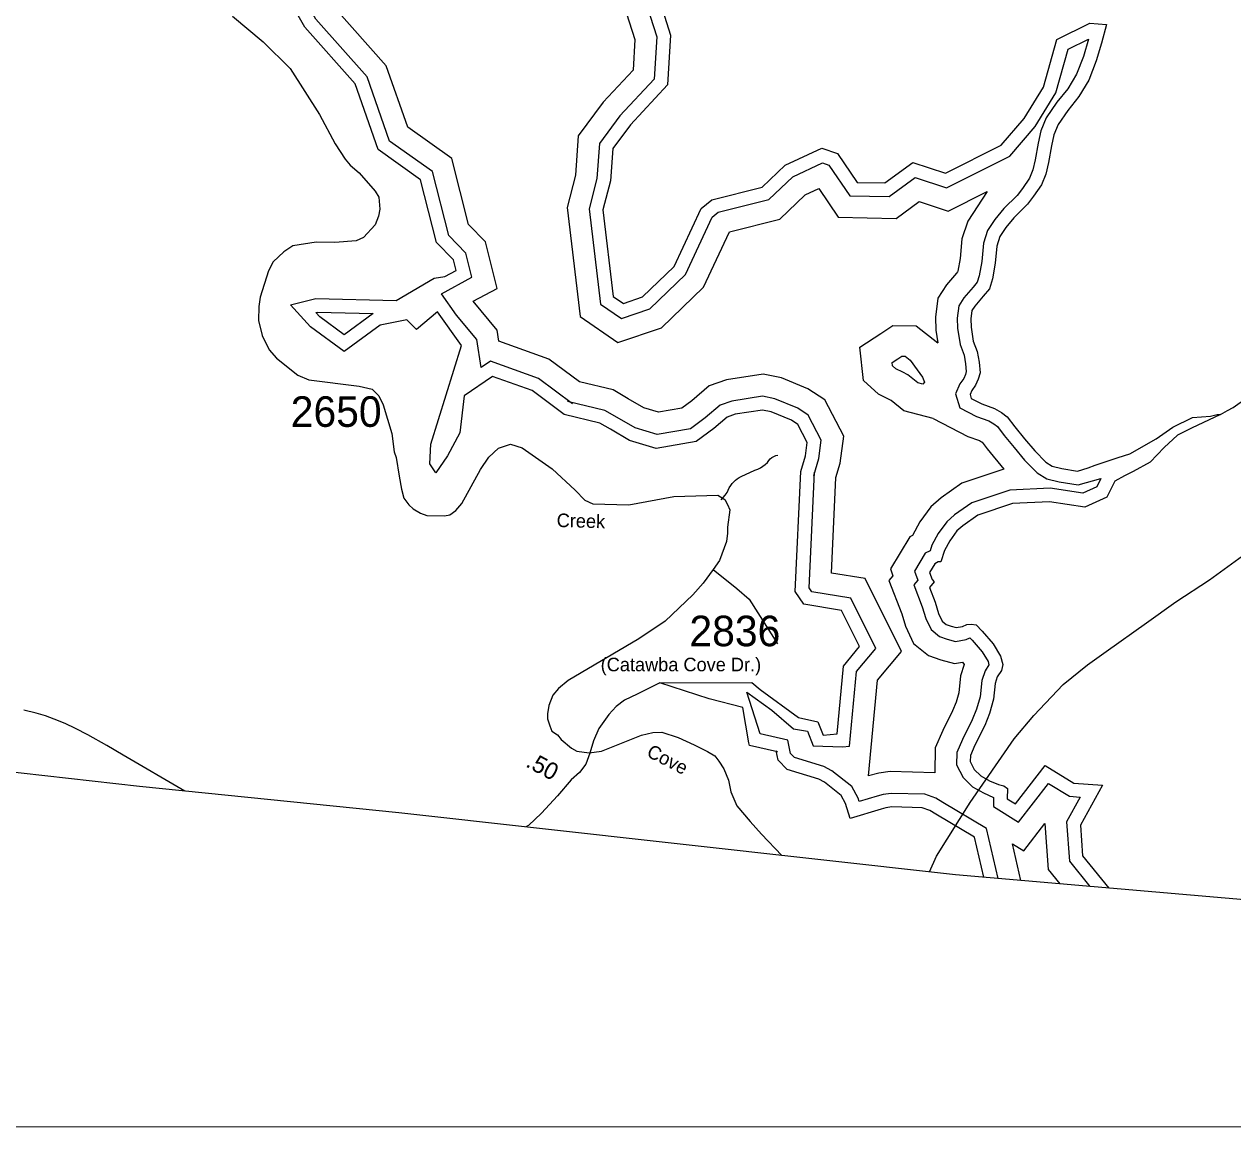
# Model space of a CAD drawing. Extents: x 1268485 to 1426702, y 514839 to 616766.
# Drawn here: x 1380280 to 1386120, y 514851 to 520182 of the extents above; entities that cross this region are included whole.
import ezdxf

# ---------------------------------------------------------------- set-up
doc = ezdxf.new("R2010")
doc.units = 0
for name, color, linetype in [('Old_Level_11', 7, 'Continuous'), ('Old_Level_17', 7, 'Continuous'), ('Old_Level_29', 7, 'Continuous'), ('Old_Level_31', 7, 'Continuous'), ('Old_Level_32', 7, 'Continuous'), ('Old_Level_35', 7, 'Continuous'), ('Old_Level_50', 7, 'Continuous'), ('Old_Level_52', 7, 'Continuous'), ('Old_Level_58', 7, 'Continuous'), ('Old_Level_60', 7, 'Continuous'), ('Old_Level_61', 7, 'Continuous'), ('Old_Level_62', 7, 'Continuous'), ('Old_Level_63', 7, 'Continuous'), ('Old_Level_8', 7, 'Continuous')]:
    doc.layers.add(name, color=color, linetype=linetype)

msp = doc.modelspace()

# ---------------------------------------------------------------- linework, layer by layer
at = {"layer": 'Old_Level_29'}
msp.add_lwpolyline([(1384653.629, 516087.565), (1384687.783, 516162.945), (1384851.453, 516422.625), (1385063.598, 516730.733), (1385159.14, 516843.649), (1385300.192, 516992.785), (1385417.556, 517087.592), (1385507.776, 517152.573), (1385702.319, 517289.991), (1385845.15, 517391.464), (1386007.246, 517498.86), (1386219.95, 517653.243)], dxfattribs=at)
at = {"layer": 'Old_Level_31'}
msp.add_line((1384843.405, 516437.698), (1384843.405, 516437.698), dxfattribs=at)
at = {"layer": 'Old_Level_32'}
for points in [[(1381285.944, 520221.123), (1381434.968, 520095.965), (1381565.364, 519968.144), (1381706.405, 519745.522), (1381783.578, 519604.386), (1381831.479, 519529.824), (1381855.429, 519500.531), (1381898.007, 519463.25), (1381975.603, 519375.82), (1381993.302, 519346.632), (1381998.611, 519288.253), (1381991.532, 519253.913), (1381975.603, 519212.705), (1381918.966, 519150.892), (1381883.568, 519135.439), (1381780.913, 519126.853), (1381690.648, 519128.571), (1381577.816, 519111.329), (1381535.298, 519082.113), (1381483.57, 519034.135), (1381460.561, 518991.21), (1381420.856, 518863.168), (1381414.659, 518818.08), (1381411.56, 518750.448), (1381430.776, 518678.236), (1381464.436, 518609.491), (1381499.867, 518568.244), (1381602.618, 518487.468), (1381655.765, 518463.408), (1381898.007, 518434.292), (1381961.875, 518418.314), (1381993.809, 518386.359), (1382015.393, 518343.104), (1382056.14, 518205.614), (1382068.497, 518116.213), (1382077.399, 518088.747), (1382091.571, 517999.379), (1382103.973, 517935.79), (1382114.602, 517892.824), (1382139.404, 517860.17), (1382158.891, 517841.266), (1382194.323, 517820.641), (1382226.211, 517808.611), (1382311.246, 517806.892), (1382336.048, 517812.048), (1382366.165, 517832.672), (1382394.51, 517867.045), (1382484.86, 518030.314), (1382525.606, 518090.466), (1382571.667, 518133.431), (1382630.129, 518154.055), (1382686.819, 518135.15), (1382831.335, 518034.539), (1382942.322, 517932.017), (1382989.757, 517882.512), (1383026.96, 517865.326), (1383202.346, 517860.17), (1383418.477, 517901.418), (1383631.065, 517906.574), (1383664.726, 517885.95), (1383678.898, 517861.889), (1383689.527, 517836.11), (1383678.399, 517753.002), (1383677.795, 517723), (1383672.989, 517683.078), (1383639.924, 517592.065), (1383609.806, 517547.381)], [(1383609.806, 517547.381), (1383561.283, 517481.772), (1383510.058, 517426.239), (1383377.728, 517298.087), (1383249.668, 517212.651), (1382908.171, 517011.878), (1382861.216, 516973.433), (1382833.859, 516940.706), (1382814.372, 516890.866), (1382809.057, 516851.337), (1382809.057, 516827.276), (1382819.686, 516792.904), (1382830.316, 516767.125), (1382856.948, 516748.737), (1382874.022, 516727.379), (1382925.246, 516684.661), (1382950.783, 516670.882), (1383009.244, 516662.288), (1383069.478, 516670.882), (1383262.578, 516748.007), (1383317.497, 516760.032), (1383361.787, 516761.749), (1383439.736, 516735.981), (1383517.685, 516701.624), (1383581.462, 516668.984), (1383616.893, 516648.369), (1383636.38, 516622.601), (1383661.182, 516584.807), (1383682.441, 516529.834), (1383694.841, 516474.862), (1383723.187, 516406.147), (1383787.523, 516330.105), (1383843.016, 516270.3), (1383940.77, 516167.041)], [(1383609.806, 517547.381), (1383723.493, 517456.142), (1383783.255, 517404.881), (1383920.401, 517189.022)]]:
    msp.add_lwpolyline(points, dxfattribs=at)
at = {"layer": 'Old_Level_35'}
for points in [[(1383647.168, 517884.413), (1383657.625, 517895.639), (1383667.365, 517907.481), (1383676.49, 517919.887), (1383681.206, 517931.523), (1383687.153, 517942.647), (1383693.919, 517953.258), (1383701.609, 517963.153), (1383708.786, 517971.867), (1383716.578, 517979.762), (1383725.395, 517986.734), (1383734.827, 517992.783), (1383744.875, 517997.806), (1383810.799, 518027.231), (1383824.128, 518032.614), (1383837.046, 518039.175), (1383849.246, 518046.865), (1383860.729, 518055.631), (1383871.392, 518065.371), (1383877.544, 518074.034), (1383884.925, 518081.775), (1383893.23, 518088.388), (1383902.355, 518093.873), (1383912.095, 518098.077), (1383922.347, 518100.896)], [(1381055.911, 516477.351), (1380758.599, 516651.844), (1380678.834, 516697.417), (1380587.893, 516749.347), (1380528.018, 516779.95), (1380477.472, 516804.147), (1380425.799, 516824.857), (1380382.841, 516841.158), (1380337.422, 516853.974), (1380278.264, 516868.892)]]:
    msp.add_lwpolyline(points, dxfattribs=at)
at = {"layer": 'Old_Level_50'}
msp.add_line((1384849.245, 516411.229), (1384849.245, 516411.229), dxfattribs=at)
at = {"layer": 'Old_Level_52'}
msp.add_lwpolyline([(1390386.565, 515584.903), (1384780.066, 516073.469), (1382090.885, 516373.285), (1380837.056, 516499.357), (1377653.026, 516857.552), (1375435.218, 517115.671), (1374243.431, 517242.496), (1370986.027, 517544.143), (1365028.634, 518085.998), (1364947.704, 518099.982), (1362624.375, 518268.785), (1357811.876, 518630.949), (1356167.665, 518747.074), (1351928.686, 519072.487), (1346107.779, 519526.78), (1342010.801, 519849.137), (1339673.829, 520032.629), (1338463.06, 520121.224), (1334735.72, 520417.336), (1328377.203, 520903.463), (1327643.106, 520964.699), (1325231.308, 521115.741), (1322642.809, 521300.009)], dxfattribs=at)
at = {"layer": 'Old_Level_58'}
for points in [[(1386060.733, 518296.055), (1385920.345, 518230.666), (1385852.102, 518196.52), (1385788.124, 518136.765), (1385720.347, 518067.017), (1385638.842, 518021.524), (1385596.189, 518000.183), (1385549.273, 517974.574), (1385510.886, 517897.746), (1385404.722, 517849.339), (1385234.115, 517874.948), (1385054.976, 517866.412), (1384888.634, 517810.925), (1384816.125, 517759.707), (1384786.27, 517734.098), (1384752.147, 517687.148), (1384726.557, 517640.197), (1384709.496, 517584.711), (1384696.7, 517584.711), (1384679.639, 517576.174), (1384654.048, 517533.492), (1384666.844, 517499.347), (1384677.349, 517487.688), (1384654.048, 517460.933), (1384681.348, 517389.929), (1384698.265, 517335.436), (1384715.386, 517298.989), (1384735.071, 517282.995), (1384759.063, 517274.331), (1384782.951, 517268.077), (1384812.991, 517273.203), (1384835.239, 517282.636), (1384855.232, 517283.866), (1384879.12, 517280.124), (1384908.545, 517250.802), (1384961.346, 517189.799), (1384998.051, 517129.154), (1385009.226, 517088.759), (1385002.664, 517060.974), (1384982.057, 517029.396), (1384971.291, 516997.613), (1384963.704, 516921.436), (1384944.327, 516852.078), (1384921.054, 516794.304), (1384873.071, 516699.212), (1384852.054, 516649.589), (1384851.438, 516620.061), (1384870.611, 516581.922), (1384901.984, 516550.959), (1384943.609, 516527.941), (1384987.183, 516509.026), (1385013.02, 516502.772), (1385030.859, 516490.109), (1385029.731, 516440.077), (1385069.306, 516415.47), (1385212.763, 516602.027), (1385351.383, 516516.663), (1385490.001, 516505.993), (1385383.371, 516313.924), (1385394.034, 516164.537), (1385520.899, 516008.91)], [(1386060.733, 518296.055), (1385920.345, 518230.666), (1385852.102, 518196.52), (1385788.124, 518136.765), (1385720.347, 518067.017), (1385638.842, 518021.524), (1385596.189, 518000.183), (1385549.273, 517974.574), (1385510.886, 517897.746), (1385404.722, 517849.339), (1385234.115, 517874.948), (1385054.976, 517866.412), (1384888.634, 517810.925), (1384816.125, 517759.707), (1384786.27, 517734.098), (1384752.147, 517687.148), (1384726.557, 517640.197), (1384709.496, 517584.711), (1384696.7, 517584.711), (1384679.639, 517576.174), (1384654.048, 517533.492), (1384666.844, 517499.347), (1384677.349, 517487.688), (1384654.048, 517460.933), (1384681.348, 517389.929), (1384698.265, 517335.436), (1384715.386, 517298.989), (1384735.071, 517282.995), (1384759.063, 517274.331), (1384782.951, 517268.077), (1384812.991, 517273.203), (1384835.239, 517282.636), (1384855.232, 517283.866), (1384879.12, 517280.124), (1384908.545, 517250.802), (1384961.346, 517189.799), (1384998.051, 517129.154), (1385009.226, 517088.759), (1385002.664, 517060.974), (1384982.057, 517029.396), (1384971.291, 516997.613), (1384963.704, 516921.436), (1384944.327, 516852.078), (1384921.054, 516794.304), (1384873.071, 516699.212), (1384852.054, 516649.589), (1384851.438, 516620.061), (1384870.611, 516581.922), (1384901.984, 516550.959), (1384943.609, 516527.941), (1384987.183, 516509.026), (1385013.02, 516502.772), (1385030.859, 516490.109), (1385029.731, 516440.077), (1385069.306, 516415.47), (1385212.763, 516602.027), (1385351.383, 516516.663), (1385490.001, 516505.993), (1385383.371, 516313.924), (1385394.034, 516164.537), (1385520.899, 516008.91)], [(1383784.487, 516697.746), (1383781.784, 516710.54), (1383752.251, 516880.775), (1383590.173, 516923.457), (1383351.323, 517000.285), (1383795.728, 517002.432), (1383836.738, 516968.752), (1384020.958, 516833.825), (1384114.792, 516812.484), (1384140.383, 516748.461), (1384207.78, 516754.473), (1384238.483, 517081.381), (1384316.765, 517175.753), (1384229.953, 517350.277), (1384046.549, 517380.155), (1384005.804, 517441.295), (1384032.697, 518020.83)], [(1383784.487, 516697.746), (1383781.784, 516710.54), (1383752.251, 516880.775), (1383590.173, 516923.457), (1383351.323, 517000.285), (1383795.728, 517002.432), (1383836.738, 516968.752), (1384020.958, 516833.825), (1384114.792, 516812.484), (1384140.383, 516748.461), (1384207.78, 516754.473), (1384238.483, 517081.381), (1384316.765, 517175.753), (1384229.953, 517350.277), (1384046.549, 517380.155), (1384005.804, 517441.295), (1384032.697, 518020.83)], [(1384917.003, 516061.536), (1384872.444, 516254.759), (1384684.572, 516366.819), (1384656.115, 516383.604), (1384619.496, 516397.073), (1384472.338, 516400.974), (1384443.126, 516397.339), (1384420.257, 516390.926), (1384271.415, 516344.964), (1384248.344, 516417.969), (1384227.164, 516456.989), (1384146.832, 516520.664), (1384119.11, 516535.748), (1383967.256, 516581.935), (1383923.112, 516627.781), (1383913.598, 516672.817), (1383920.016, 516667.72), (1383784.487, 516697.746)], [(1384917.003, 516061.536), (1384872.444, 516254.759), (1384684.572, 516366.819), (1384656.115, 516383.604), (1384619.496, 516397.073), (1384472.338, 516400.974), (1384443.126, 516397.339), (1384420.257, 516390.926), (1384271.415, 516344.964), (1384248.344, 516417.969), (1384227.164, 516456.989), (1384146.832, 516520.664), (1384119.11, 516535.748), (1383967.256, 516581.935), (1383923.112, 516627.781), (1383913.598, 516672.817), (1383920.016, 516667.72), (1383784.487, 516697.746)]]:
    msp.add_lwpolyline(points, dxfattribs=at)
at = {"layer": 'Old_Level_60'}
for points in [[(1383315.628, 520405.001), (1383402.745, 520128.605), (1383388.802, 519889.258), (1383208.998, 519696.48), (1383123.694, 519581.238), (1383112.802, 519425.43), (1383076.815, 519285.021), (1383126.745, 518867.176), (1383175.753, 518833.342), (1383267.821, 518864.305), (1383420.79, 519012.25), (1383551.818, 519291.838), (1383602.774, 519333.464), (1383845.761, 519394.262), (1383956.796, 519500.376), (1384133.799, 519582.497), (1384210.572, 519556.888), (1384304.77, 519417.895), (1384438.771, 519415.229), (1384573.114, 519514.206), (1384730.926, 519462.988), (1385000.716, 519597.52), (1385111.752, 519726.6), (1385204.363, 519877.003), (1385269.745, 520107.485), (1385429.788, 520186.327), (1385509.142, 520179.884)], [(1382889.576, 518296.338), (1382734.318, 518412.465), (1382542.385, 518480.757), (1382405.899, 518386.856), (1382384.573, 518207.592), (1382324.86, 518096.619), (1382269.412, 518015.523), (1382239.556, 518058.205), (1382244.816, 518152.928), (1382393.103, 518630.144), (1382277.943, 518792.335), (1382175.578, 518706.971), (1382128.661, 518753.921), (1382000.705, 518728.312), (1381825.832, 518600.266), (1381663.755, 518719.776), (1381566.812, 518826.268), (1381689.346, 518856.358), (1382077.478, 518847.822), (1382260.882, 518954.526), (1382312.064, 518963.063), (1382367.511, 518992.941), (1382354.827, 519043.52), (1382272.806, 519127.182), (1382195.809, 519430.761), (1381990.757, 519575.99), (1381879.824, 519893.359), (1381635.812, 520167.411), (1381603.824, 520223.852)], [(1385509.142, 520179.884), (1385485.767, 520090.773), (1385460.033, 520005.112), (1385424.046, 519911.506), (1385376.372, 519832.868), (1385323.058, 519765.816), (1385275.589, 519697.021), (1385254.468, 519647.399), (1385243.396, 519595.06), (1385229.76, 519513.295), (1385216.534, 519457.777), (1385195.516, 519406.463), (1385156.351, 519350.637), (1385127.541, 519311.831), (1385062.129, 519246.676), (1385023.067, 519199.873), (1384994.257, 519156.146), (1384979.288, 519110.521), (1384971.496, 519026.963), (1384957.963, 518952.529), (1384944.942, 518903.572), (1384914.184, 518868.098), (1384873.174, 518820.475), (1384858.718, 518798.637), (1384853.899, 518759.318), (1384855.027, 518719.128), (1384865.69, 518650.795), (1384884.554, 518600.352), (1384893.577, 518550.114), (1384898.498, 518498.287), (1384889.886, 518468.144), (1384877.173, 518438.002), (1384858.718, 518412.934), (1384850.311, 518392.582), (1384855.847, 518374.435), (1384907.315, 518347.984), (1384968.933, 518326.197), (1385002.562, 518305.845), (1385030.141, 518284.777), (1385067.051, 518236.435), (1385113.905, 518179.688), (1385162.81, 518120.428), (1385215.713, 518066.857), (1385247.292, 518046.506), (1385293.121, 518035.741), (1385368.887, 518023.54), (1385421.317, 518038.597), (1385455.438, 518051.401), (1385566.333, 518089.815), (1385621.781, 518106.888), (1385749.736, 518179.447), (1385830.775, 518234.934), (1385924.61, 518281.884), (1386012.648, 518288.775), (1386044.739, 518296.362), (1386060.733, 518296.055)], [(1384501.087, 518565.1), (1384521.285, 518578.634), (1384537.279, 518578.326), (1384560.963, 518559.769), (1384593.976, 518513.171), (1384621.248, 518476.518), (1384630.68, 518452.527), (1384622.478, 518442.838), (1384598.59, 518449.092), (1384549.48, 518488.616), (1384525.694, 518500.611), (1384491.962, 518517.682), (1384476.276, 518531.933), (1384474.636, 518547.568), (1384501.087, 518565.1)], [(1384032.697, 518020.83), (1384055.079, 518097.212), (1384063.609, 518161.235), (1384017.962, 518248.41), (1383986.903, 518268.664), (1383888.602, 518309.623), (1383846.71, 518318.001), (1383714.852, 518297.797), (1383676.818, 518284.235), (1383612.037, 518228.876), (1383526.195, 518165.504), (1383334.441, 518132.647), (1383205.239, 518171.485), (1383112.471, 518225.258), (1383061.289, 518255.135), (1382889.576, 518296.338)]]:
    msp.add_lwpolyline(points, dxfattribs=at)
at = {"layer": 'Old_Level_61'}
msp.add_line((1385095.675, 516045.966), (1385054.696, 516223.664), dxfattribs=at)
for points in [[(1382296.192, 518879.974), (1382443.573, 518959.39), (1382414.143, 519076.746), (1382332.056, 519160.475), (1382253.467, 519470.332), (1382045.784, 519617.424), (1381937.475, 519927.283), (1381689.457, 520205.834), (1381670.374, 520239.505), (1381683.684, 520487.501), (1381471.55, 520759.111), (1381473.393, 521234.275), (1381505.778, 521474.289), (1381448.129, 521577.884), (1381277.965, 521545.468), (1381126.593, 521434.139), (1381044.52, 521493.953), (1381021.915, 521570.934), (1381037.221, 521900.515), (1381123.76, 522427.118), (1381110.777, 522684.509), (1381057.635, 522822.076)], [(1382450.269, 518843.74), (1382565.273, 518905.709), (1382509.048, 519129.908), (1382426.857, 519213.745), (1382345.72, 519533.646), (1382133.827, 519683.719), (1382029.718, 519981.562), (1381776.907, 520265.496), (1381790.627, 520521.137), (1381576.677, 520795.071), (1381578.353, 521227.021), (1381614.49, 521494.841), (1381502.987, 521695.209), (1381234.937, 521644.146), (1381132.055, 521568.48), (1381127.605, 521583.636), (1381141.811, 521889.53), (1381222.422, 522380.061)], [(1383163.488, 520320.17), (1383230.608, 520107.225), (1383222.067, 519960.617), (1383077.635, 519805.764), (1382956.975, 519642.758), (1382943.694, 519452.78), (1382903.631, 519296.464), (1382966.479, 518770.509), (1383149.144, 518644.401), (1383358.727, 518714.884), (1383561.953, 518911.436), (1383687.22, 519178.731), (1383930.982, 519239.722), (1384054.235, 519357.512), (1384119.179, 519387.644), (1384213.085, 519249.081), (1384493.313, 519243.507), (1384603.777, 519324.891), (1384744.621, 519279.18), (1384932.861, 519373.046)], [(1383257.113, 520372.373), (1383336.538, 520120.382), (1383324.673, 519916.703), (1383158.474, 519738.512), (1383059.571, 519604.9), (1383047.76, 519435.949), (1383010.206, 519289.422), (1383065.104, 518829.996), (1383165.519, 518760.672), (1383302.785, 518806.835), (1383475.084, 518973.475), (1383604.897, 519250.47), (1383632.928, 519273.37), (1383878.538, 519334.824), (1383994.272, 519445.429), (1384137.766, 519512.003), (1384168.724, 519501.676), (1384269.506, 519352.966), (1384459.749, 519349.182), (1384584.907, 519441.393), (1384736.193, 519392.293), (1385041.835, 519544.702), (1385164.894, 519687.76), (1385265.006, 519850.344), (1385324.909, 520061.514), (1385422.977, 520109.825)], [(1385422.977, 520109.825), (1385397.901, 520026.355), (1385364.901, 519940.517), (1385322.42, 519870.446), (1385270.314, 519804.912), (1385217.812, 519728.825), (1385191.594, 519667.224), (1385178.906, 519607.253), (1385165.408, 519526.31), (1385153.883, 519477.936), (1385137.58, 519438.132), (1385103.141, 519389.044), (1385077.771, 519354.87), (1385013.686, 519291.036), (1384970.315, 519239.07), (1384934.643, 519184.928), (1384914.64, 519123.963), (1384906.428, 519035.895), (1384893.875, 518966.854), (1384885.429, 518935.097), (1384864.536, 518911), (1384820.748, 518860.151), (1384795.469, 518821.965), (1384788.17, 518762.406), (1384789.553, 518713.126), (1384801.888, 518634.072), (1384821.019, 518582.919), (1384828.511, 518541.198), (1384832.004, 518504.409), (1384827.884, 518489.987), (1384819.73, 518470.653), (1384801.129, 518445.387), (1384780.692, 518395.913), (1384801.181, 518328.756), (1384881.264, 518287.597), (1384940.717, 518266.576), (1384965.55, 518251.547), (1384983.323, 518237.971), (1385015.656, 518195.622), (1385063.302, 518137.916), (1385114.065, 518076.404), (1385174.099, 518015.614), (1385221.264, 517985.218), (1385280.386, 517971.33), (1385372.919, 517956.429), (1385482.592, 517987.924)], [(1384932.861, 519373.046), (1384839.259, 519230.981), (1384811.204, 519145.471), (1384802.318, 519050.186), (1384791.334, 518989.774), (1384790.207, 518985.537), (1384785.097, 518979.642), (1384736.866, 518923.633), (1384694.271, 518859.289), (1384683.004, 518767.347), (1384684.794, 518703.522), (1384694.255, 518642.889)], [(1382928.877, 518348.883), (1382765.669, 518470.957), (1382532.805, 518553.812), (1382488.189, 518523.116), (1382466.679, 518658.724), (1382369.805, 518776.296), (1382296.192, 518879.974)], [(1382963.589, 518454.025), (1382815.83, 518564.543), (1382574.284, 518650.487), (1382565.889, 518703.415), (1382450.269, 518843.74)], [(1381966.55, 518784.629), (1381825.968, 518681.692), (1381707.914, 518768.741), (1381689.603, 518788.855), (1381696.573, 518790.566), (1381966.55, 518784.629)], [(1384671.393, 518277.419), (1384530.636, 518314.27), (1384469.07, 518363.818), (1384459.121, 518368.836), (1384407.472, 518394.974), (1384335.321, 518460.524), (1384318.464, 518621.181), (1384419.523, 518688.162)], [(1384418.906, 518687.75), (1384477.688, 518727.136), (1384589.477, 518724.987), (1384694.255, 518642.889)], [(1384202.168, 517992.483), (1384222.466, 518061.753), (1384239.872, 518192.393), (1384148.444, 518366.994), (1384066.973, 518420.121), (1383938.625, 518473.6), (1383850.637, 518491.197), (1383672.902, 518463.964), (1383589.895, 518434.364), (1383505.824, 518362.521), (1383457.457, 518326.816), (1383345.151, 518307.572), (1383273.499, 518329.111), (1383198.253, 518372.728), (1383125.563, 518415.159), (1382963.589, 518454.025)], [(1384095.666, 518002.377), (1384119.459, 518083.574), (1384131.403, 518173.219), (1384068.148, 518294.02), (1384017.699, 518326.917), (1383907.841, 518372.691), (1383848.22, 518384.615), (1383698.718, 518361.707), (1383643.386, 518341.976), (1383571.186, 518280.278), (1383499.757, 518227.547), (1383338.56, 518199.925), (1383231.493, 518232.11), (1383145.464, 518281.977), (1383086.01, 518316.683), (1382904.886, 518360.144)], [(1384671.393, 518277.419), (1384839.581, 518190.979), (1384895.568, 518171.184), (1384906.333, 518164.669), (1384908.414, 518163.079), (1384933.425, 518130.321), (1385014.093, 518032.62)], [(1383835.514, 516753.649), (1383772.496, 516956.2), (1383891.922, 516869.129), (1383997.698, 516778.643), (1384064.235, 516766.693), (1384091.533, 516696.693), (1384234.041, 516690.938), (1384268.003, 516693.968), (1384301.918, 517055.079), (1384394.537, 517166.734), (1384273.716, 517409.63), (1384085.304, 517440.323), (1384072.348, 517459.764), (1384098.243, 518017.788)], [(1384360.045, 516551.225), (1384403.414, 517012.995), (1384518.973, 517152.304), (1384343.737, 517504.594), (1384180.76, 517531.144), (1384202.168, 517992.483)], [(1385014.093, 518032.62), (1384810.768, 517964.796), (1384711.142, 517894.422), (1384660.019, 517850.572), (1384607.642, 517778.503), (1384571.978, 517713.073), (1384558.869, 517706.513), (1384465.425, 517550.663), (1384477.619, 517518.121), (1384457.96, 517495.549), (1384520.087, 517333.966), (1384538.832, 517273.583), (1384577.548, 517191.165), (1384649.931, 517132.355), (1384708.382, 517111.246), (1384775.358, 517093.711), (1384813.28, 517100.183), (1384822.356, 517089.696), (1384803.458, 517033.898), (1384795.408, 516953.08), (1384782.555, 516907.072), (1384765.498, 516864.73), (1384718.197, 516770.987), (1384682.17, 516685.93), (1384679.675, 516566.14)], [(1385482.592, 517987.924), (1385462.557, 517947.825), (1385395.212, 517917.118), (1385237.456, 517940.799), (1385042.805, 517931.524), (1384858.686, 517870.106), (1384775.747, 517811.521), (1384737.712, 517778.895), (1384696.568, 517722.284), (1384665.78, 517665.798), (1384657.354, 517638.396), (1384633.189, 517626.304), (1384581.501, 517540.096), (1384597.89, 517496.361), (1384578.63, 517474.247), (1384619.324, 517368.405), (1384636.944, 517311.646), (1384662.371, 517257.518), (1384702.325, 517225.056), (1384739.569, 517211.606), (1384780.031, 517201.013), (1384831.565, 517209.808), (1384849.216, 517217.29), (1384860.515, 517206.03), (1384908.092, 517151.063), (1384937.225, 517102.928), (1384941.501, 517087.473), (1384941.442, 517087.224), (1384922.57, 517058.307), (1384906.74, 517011.569), (1384898.975, 516933.607), (1384882.107, 516873.229), (1384861.224, 516821.391), (1384813.505, 516726.817), (1384786.714, 516663.566), (1384785.497, 516605.143), (1384816.834, 516542.804), (1384862.323, 516497.909), (1384914.603, 516469.001), (1384964.264, 516447.442), (1384963.288, 516404.123), (1385085.109, 516328.379), (1385228.722, 516515.138), (1385330.505, 516452.459), (1385382.988, 516448.419), (1385316.532, 516328.714), (1385330.062, 516139.163), (1385429.769, 516016.852)], [(1384985.724, 516055.547), (1384930.093, 516296.776), (1384718.047, 516423.255), (1384684.338, 516443.138), (1384632.02, 516462.38), (1384469.139, 516466.699), (1384430.143, 516461.846), (1384401.715, 516453.874), (1384314.34, 516426.893), (1384309.015, 516443.742), (1384278.434, 516500.08), (1384183.16, 516575.598), (1384144.599, 516596.58), (1384002.682, 516639.745), (1383983.424, 516659.745), (1383969.876, 516723.881), (1383835.514, 516753.649)], [(1384679.675, 516566.14), (1384464.018, 516571.859), (1384409.372, 516565.057), (1384360.045, 516551.225)], [(1385054.696, 516223.664), (1385110.394, 516189.033), (1385211.832, 516320.947), (1385227.706, 516098.566), (1385283.961, 516029.558)]]:
    msp.add_lwpolyline(points, dxfattribs=at)
at = {"layer": 'Old_Level_62'}
for points in [[(1386060.733, 518296.055), (1386093.336, 518316.713), (1386121.531, 518330.093), (1386243.435, 518417.906), (1386310.384, 518460.865), (1386354.88, 518485.42), (1386375.386, 518511.257), (1386402.247, 518552.575), (1386421.522, 518612.091), (1386452.588, 518663.969), (1386469.197, 518693.189), (1386483.653, 518713.438), (1386514.206, 518738.249), (1386976.322, 519258.729)], [(1383351.323, 517000.285), (1383241.37, 516945.427), (1383180.879, 516917.079), (1383140.176, 516885.911), (1383105.42, 516848.028), (1383055.9, 516779.284), (1383030.678, 516719.87), (1383013.352, 516660.354), (1382994.282, 516608.219), (1382963.524, 516566.953), (1382922.719, 516531.684), (1382856.999, 516455.045), (1382779.285, 516370.461), (1382716.129, 516311.816), (1382704.26, 516304.9)]]:
    msp.add_lwpolyline(points, dxfattribs=at)
at = {"layer": 'Old_Level_63'}
msp.add_line((1401916.107, 514851.377), (1368032.91, 514859.624), dxfattribs=at)

# ---------------------------------------------------------------- texts
at = {"layer": 'Old_Level_11'}
for s, rotation, p in [('Creek', 358.3161583, (1382852.298, 517753.622)), ('Cove', 332.8972361, (1383282.853, 516648.071))]:
    msp.add_text(s, height=65.6167, rotation=rotation, dxfattribs=at).set_placement(p)
msp.add_text('(Catawba Cove Dr.)', height=65.61666, dxfattribs=at).set_placement((1383065.541, 517056.348))
at = {"layer": 'Old_Level_17'}
msp.add_text('.50', height=82.0208, rotation=331.6485667, dxfattribs=at).set_placement((1382698.72, 516598.168))
at = {"layer": 'Old_Level_8'}
for s, p in [('2650', (1381568.012, 518236.986)), ('2836', (1383494.437, 517177.424))]:
    msp.add_text(s, height=147.6375, dxfattribs=at).set_placement(p)

doc.saveas('drawing.dxf')
